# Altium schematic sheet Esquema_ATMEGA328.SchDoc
size A4
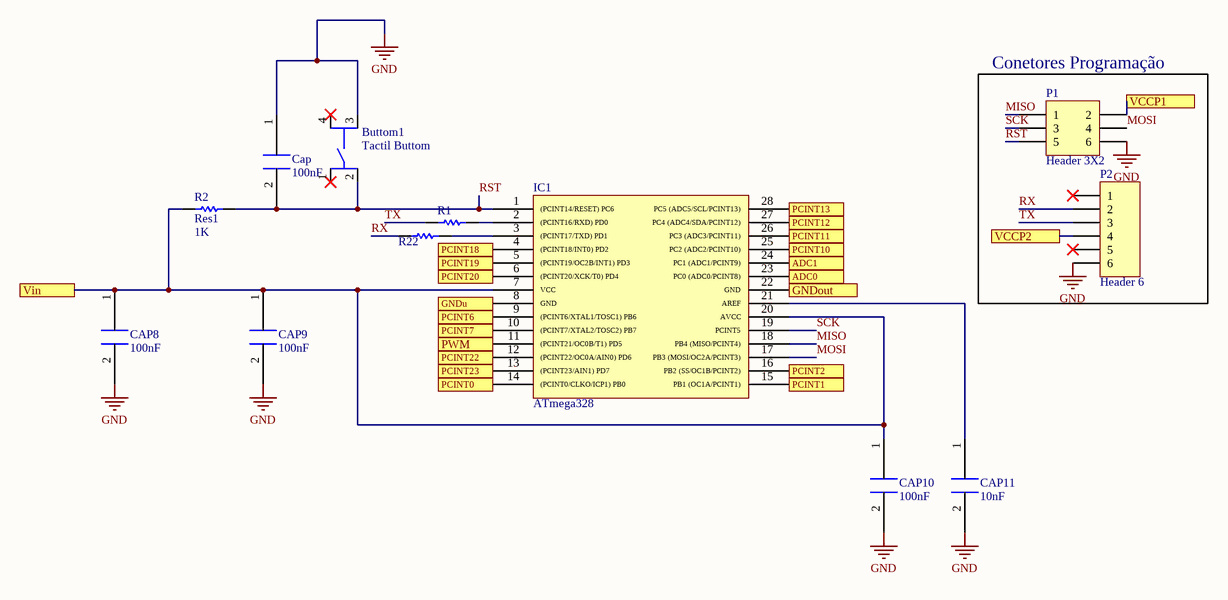
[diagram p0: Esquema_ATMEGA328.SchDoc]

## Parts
Buttom1  Tactil Buttom  [Tactil Buttom]
Cap  100nF  [Capacitor Eletro]
CAP8  100nF  [Capacitor Eletro]
CAP9  100nF  [Capacitor Eletro]
CAP10  100nF  [Capacitor Eletro]
CAP11  10nF  [Capacitor Eletro]
IC1  ATmega328  [ATmega328]
P1  Header 3X2  [HDR2X3]
P2  Header 6  [HDR1X6]
R1  Res1  [AXIAL-0.3]  (value not drawn)
R2  Res1  value 1K  [AXIAL-0.3]
R22  Res1  [AXIAL-0.3]  (value not drawn)

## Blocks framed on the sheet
Conetores Programação: P1 P2

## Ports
ADC0, ADC1, GNDout, GNDu, PCINT0, PCINT1, PCINT2, PCINT6, PCINT7, PCINT10, PCINT11, PCINT12, PCINT13, PCINT18, PCINT19, PCINT20, PCINT22, PCINT23, PWM, VCCP1, VCCP2, Vin

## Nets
GND: Buttom1.3 Cap.1 CAP8.2 CAP9.2 CAP10.2 CAP11.2 P1.6 P2.6
ADC0: IC1.23(PC0_(ADC0/PCINT8)) ; port ADC0
ADC1: IC1.24(PC1_(ADC1/PCINT9)) ; port ADC1
GNDout: IC1.22(GND) ; port GNDout
GNDu: IC1.8(GND) ; port GNDu
MISO: IC1.18(PB4_(MISO/PCINT4)) P1.1
MOSI: IC1.17(PB3_(MOSI/OC2A/PCINT3)) P1.4
PCINT0: IC1.14((PCINT0/CLKO/ICP1)_PB0) ; port PCINT0
PCINT1: IC1.15(PB1_(OC1A/PCINT1)) ; port PCINT1
PCINT2: IC1.16(PB2_(SS/OC1B/PCINT2)) ; port PCINT2
PCINT6: IC1.9((PCINT6/XTAL1/TOSC1)_PB6) ; port PCINT6
PCINT7: IC1.10((PCINT7/XTAL2/TOSC2)_PB7) ; port PCINT7
PCINT10: IC1.25(PC2_(ADC2/PCINT10)) ; port PCINT10
PCINT11: IC1.26(PC3_(ADC3/PCINT11)) ; port PCINT11
PCINT12: IC1.27(PC4_(ADC4/SDA/PCINT12)) ; port PCINT12
PCINT13: IC1.28(PC5_(ADC5/SCL/PCINT13)) ; port PCINT13
PCINT18: IC1.4((PCINT18/INT0)_PD2) ; port PCINT18
PCINT19: IC1.5((PCINT19/OC2B/INT1)_PD3) ; port PCINT19
PCINT20: IC1.6((PCINT20/XCK/T0)_PD4) ; port PCINT20
PCINT22: IC1.12((PCINT22/OC0A/AIN0)_PD6) ; port PCINT22
PCINT23: IC1.13((PCINT23/AIN1)_PD7) ; port PCINT23
PWM: IC1.11((PCINT21/OC0B/T1)_PD5) ; port PWM
RST: Buttom1.2 Cap.2 IC1.1((PCINT14/RESET)_PC6) P1.5 R2.2
RX: P2.2 R22.1
SCK: IC1.19(PCINT5) P1.3
TX: P2.3 R1.1
VCCP1: P1.2 ; port VCCP1
VCCP2: P2.4 ; port VCCP2
Vin: CAP8.1 CAP9.1 CAP10.1 IC1.7(VCC) IC1.20(AVCC) R2.1 ; port Vin
NetCAP11_1: CAP11.1 IC1.21(AREF)
NetIC1_2: IC1.2((PCINT16/RXD)_PD0) R1.2
NetIC1_3: IC1.3((PCINT17/TXD)_PD1) R22.2

Not connected (* = marked no-connect by the designer): Buttom1 1* 4*; P2 1* 5*

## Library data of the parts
Cap CAP8-CAP11 = 33pF: Condensador
P1 = Header 3X2: Header, 3-Pin, Dual row
P2 = Header 6: Header, 6-Pin
R1 R22 = Res1: Resistor; Value: 1K
R2 = Res1: Resistor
